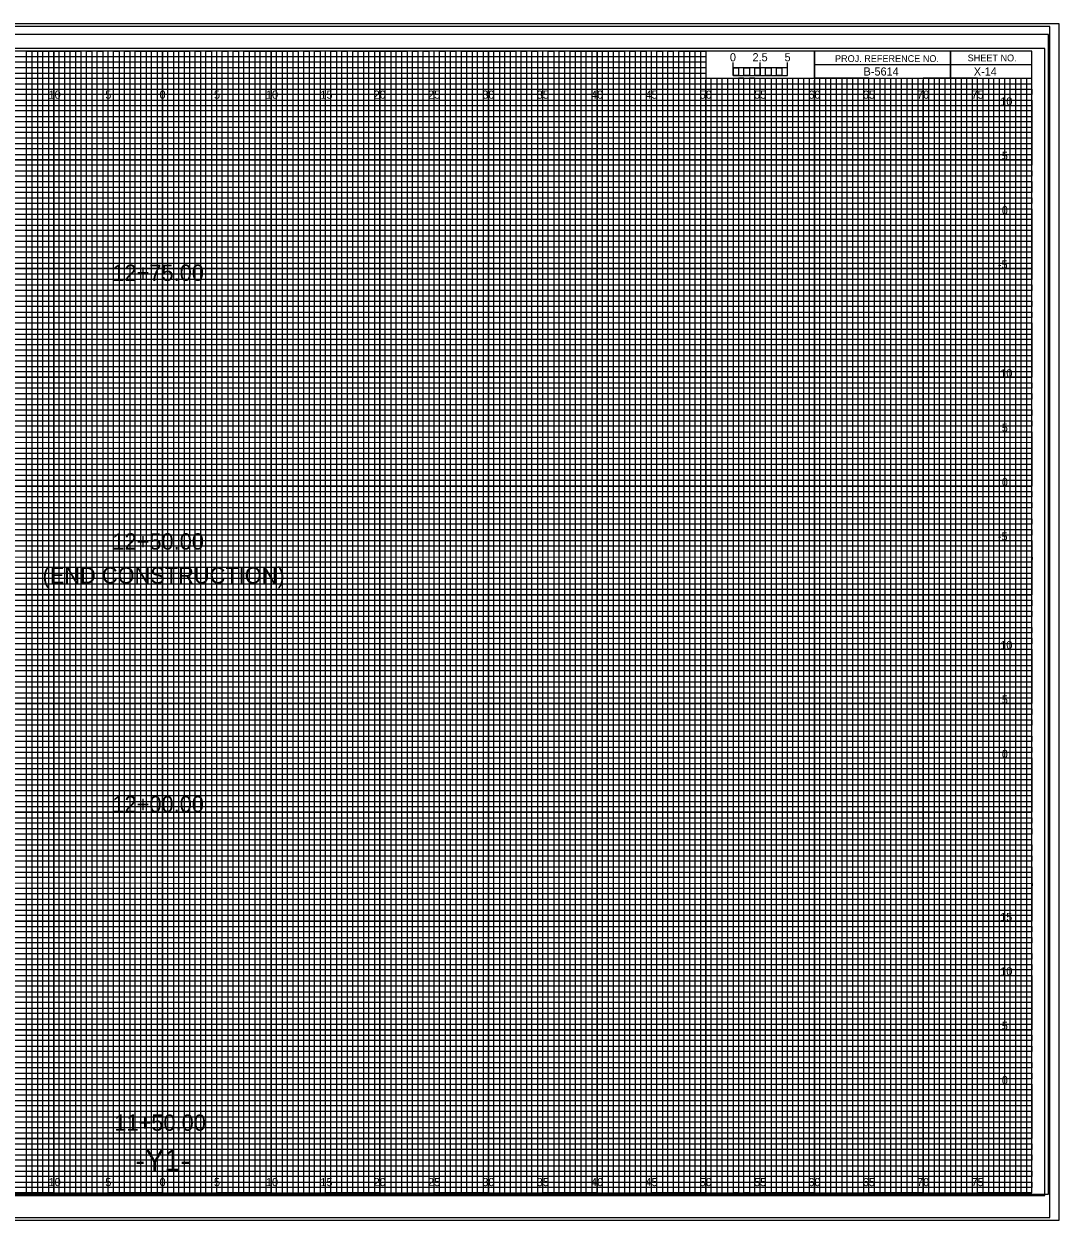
# Model space of a CAD drawing. Extents: x -8 to 162, y 108 to 218.
# Drawn here: x 67.2 to 162.5, y 107.5 to 217.5 of the extents above; entities that cross this region are included whole.
import ezdxf

# ---------------------------------------------------------------- set-up
doc = ezdxf.new("R2010")
doc.units = 0
for name, color, linetype in [('Prop XS Alignment Label', 7, 'Continuous'), ('Prop XS Bar Scale Labels', 7, 'Continuous'), ('Prop XS Elevation Labels', 7, 'Continuous'), ('Prop XS Offset Labels', 7, 'Continuous'), ('Prop XS Project Number', 7, 'Continuous'), ('Prop XS Sheet Number', 7, 'Continuous'), ('Prop XS Station Labels', 7, 'Continuous'), ('Sheet Cross Section CELL', 7, 'Continuous'), ('Sheet Cross Section Grid Major CELL', 7, 'Continuous'), ('Sheet Cross Section Grid Middle CELL', 7, 'Continuous'), ('Sheet Cross Section Grid Minor 1 CELL', 7, 'Continuous'), ('Sheet Cross Section Grid Minor 2 CELL', 7, 'Continuous'), ('Sheet Cross Section Scale CELL', 7, 'Continuous'), ('Sheet Cutting Line CELL', 7, 'Continuous'), ('Sheet DOT Grid CELL', 7, 'Continuous'), ('Sheet Plot Border Inside CELL', 7, 'Continuous'), ('Sheet Plot Border Outside CELL', 7, 'Continuous'), ('Stewart Plot Border DJ1055', 7, 'Continuous'), ('Stewart Plot Border DJ1055 Invisible', 7, 'Continuous'), ('Stewart Plot Border Xerox6279 and LJ5000', 7, 'Continuous')]:
    doc.layers.add(name, color=color, linetype=linetype)

msp = doc.modelspace()

# ---------------------------------------------------------------- linework, layer by layer
at = {"layer": 'Sheet Cross Section CELL'}
for p, q in [((152.5, 215), (152.5, 212.5)), ((152.5, 212.5), (152.5, 215)), ((160, 213.75), (140, 213.75)), ((140, 213.75), (140, 212.5)), ((140, 212.5), (160, 212.5))]:
    msp.add_line(p, q, dxfattribs=at)
for points in [[(160, 215), (0, 215), (0, 110), (160, 110)], [(140, 215), (130, 215), (130, 212.52), (140, 212.52)], [(160, 215), (140, 215), (140, 212.5), (160, 212.5)]]:
    msp.add_lwpolyline(points, close=True, dxfattribs=at)
at = {"layer": 'Sheet Cross Section Grid Major CELL'}
for p, q in [((75, 215), (70, 215)), ((70, 215), (70, 110)), ((75, 110), (75, 215)), ((85, 215), (80, 215)), ((80, 215), (80, 110)), ((85, 110), (85, 215)), ((95, 215), (90, 215)), ((90, 215), (90, 110)), ((95, 110), (95, 215)), ((105, 215), (100, 215)), ((100, 215), (100, 110)), ((105, 110), (105, 215)), ((115, 215), (110, 215)), ((110, 215), (110, 110)), ((115, 110), (115, 215)), ((125, 215), (120, 215)), ((120, 215), (120, 110)), ((125, 110), (125, 215)), ((130, 215), (130, 110)), ((135, 110), (135, 212.5)), ((145, 212.5), (140, 212.5)), ((140, 212.5), (140, 110)), ((145, 110), (145, 212.5)), ((155, 212.5), (150, 212.5)), ((150, 212.5), (150, 110)), ((155, 110), (155, 212.5)), ((70, 110), (65, 110)), ((80, 110), (75, 110)), ((90, 110), (85, 110)), ((100, 110), (95, 110)), ((110, 110), (105, 110)), ((120, 110), (115, 110)), ((130, 110), (125, 110)), ((140, 110), (135, 110)), ((150, 110), (145, 110)), ((160, 110), (155, 110)), ((160, 110), (160, 110))]:
    msp.add_line(p, q, dxfattribs=at)
for points in [[(0, 210), (160, 210), (160, 205), (0, 205)], [(0, 200), (160, 200), (160, 195), (0, 195)], [(0, 190), (160, 190), (160, 185), (0, 185)], [(0, 180), (160, 180), (160, 175), (0, 175)], [(0, 170), (160, 170), (160, 165), (0, 165)], [(0, 160), (160, 160), (160, 155), (0, 155)], [(0, 150), (160, 150), (160, 145), (0, 145)], [(0, 140), (160, 140), (160, 135), (0, 135)], [(0, 130), (160, 130), (160, 125), (0, 125)], [(0, 120), (160, 120), (160, 115), (0, 115)]]:
    msp.add_lwpolyline(points, dxfattribs=at)
at = {"layer": 'Sheet Cross Section Grid Middle CELL'}
for points in [[(62.5, 110), (67.5, 110), (67.5, 215), (72.5, 215), (72.5, 110), (77.5, 110), (77.5, 215), (82.5, 215), (82.5, 110), (87.5, 110), (87.5, 215), (92.5, 215), (92.5, 110), (97.5, 110), (97.5, 215), (102.5, 215), (102.5, 110), (107.5, 110), (107.5, 215), (112.5, 215), (112.5, 110), (117.5, 110), (117.5, 215), (122.5, 215), (122.5, 110), (127.5, 110), (127.5, 215), (129.97, 215), (130, 215), (130, 212.5), (132.5, 212.5), (132.5, 110), (137.5, 110), (137.5, 212.5), (142.5, 212.5), (142.5, 110), (147.5, 110), (147.5, 212.5), (152.5, 212.5), (152.5, 110), (157.5, 110), (157.5, 212.5)], [(0, 212.5), (137.5, 212.5)], [(0, 202.5), (160, 202.5), (160, 207.5), (0, 207.5)], [(0, 192.5), (160, 192.5), (160, 197.5), (0, 197.5)], [(0, 182.5), (160, 182.5), (160, 187.5), (0, 187.5)], [(0, 172.5), (160, 172.5), (160, 177.5), (0, 177.5)], [(0, 162.5), (160, 162.5), (160, 167.5), (0, 167.5)], [(0, 152.5), (160, 152.5), (160, 157.5), (0, 157.5)], [(0, 142.5), (160, 142.5), (160, 147.5), (0, 147.5)], [(0, 132.5), (160, 132.5), (160, 137.5), (0, 137.5)], [(0, 122.5), (160, 122.5), (160, 127.5), (0, 127.5)], [(0, 112.5), (160, 112.5), (160, 117.5), (0, 117.5)]]:
    msp.add_lwpolyline(points, dxfattribs=at)
at = {"layer": 'Sheet Cross Section Grid Minor 1 CELL'}
for p, q in [((0, 214.5), (130, 214.5)), ((130, 213.99), (0, 213.99)), ((0, 213.5), (130, 213.5)), ((130, 214.5), (130, 213.99)), ((130, 213.5), (130, 212.94)), ((130, 212.94), (0, 212.94)), ((0, 212), (160, 212))]:
    msp.add_line(p, q, dxfattribs=at)
for points in [[(0, 211.5), (135, 211.5), (160, 211.5), (160, 211), (0, 211)], [(0, 210.5), (160, 210.5), (160, 209.5), (0, 209.5)], [(0, 209), (160, 209), (160, 208.5), (0, 208.49)], [(0, 208), (160, 208), (160, 207), (0, 207)], [(0, 206.5), (160, 206.5), (160, 206), (0, 206)], [(0, 205.5), (160, 205.5), (160, 204.5), (0, 204.5)], [(0, 204), (160, 204), (160, 203.5), (0, 203.5)], [(0, 203), (160, 203), (160, 202), (0, 202)], [(0, 201.5), (160, 201.5), (160, 201), (0, 201)], [(0, 200.5), (160, 200.5), (160, 199.5), (0, 199.5)], [(0, 199), (160, 199), (160, 198.5), (0, 198.5)], [(0, 198), (160, 198), (160, 196.97), (160, 196.5), (160, 196), (0, 196)], [(0, 197), (160, 197), (160, 196.5), (0, 196.5)], [(0, 195.5), (160, 195.5), (160, 194.5), (0, 194.52)], [(0, 194.52), (160, 194.5), (160, 194), (0, 194)], [(0, 193.5), (160, 193.5), (160, 193), (0, 193)], [(0, 192), (160, 192), (160, 191.5), (0, 191.5)], [(0, 191), (160, 191), (160, 190.5), (0, 190.5)], [(-0.04, 189.44), (160, 189.44), (160, 188.94), (-0.04, 188.94)], [(0, 188.5), (160, 188.5), (160, 188), (0, 188)], [(0, 187), (160, 187), (160, 186.5), (0, 186.5)], [(0, 186), (160, 186), (160, 185.5), (0, 185.5)], [(0, 184.5), (160, 184.5), (160, 184), (0, 184)], [(0, 183.5), (160, 183.5), (160, 183), (0, 183)], [(0, 182), (160, 182), (160, 181.5), (0, 181.5)], [(0, 181), (160, 181), (160, 180.5), (0, 180.5)], [(0, 179.5), (160, 179.5), (160, 178.99), (0, 179)], [(0, 178.5), (160, 178.5), (160, 178), (0, 178)], [(0, 177), (160, 177), (160, 176.5), (0, 176.5)], [(0, 176), (160, 176), (160, 175.5), (0, 175.5)], [(0, 174.5), (160, 174.5), (160, 174), (0, 174)], [(0, 173.5), (160, 173.5), (160, 173), (0, 173)], [(0, 172), (160, 172), (160, 171.5), (0, 171.5)], [(0, 171), (160, 171), (160, 170.5), (0, 170.5)], [(0, 169.5), (160, 169.5), (160, 169), (0, 169)], [(0, 168.5), (160.03, 168.46), (160, 168), (0, 168)], [(0, 167), (160, 167), (160, 166.5), (0, 166.5)], [(0, 166), (160, 166), (160, 165.5), (0, 165.5)], [(0, 164.5), (160, 164.5), (160, 164), (0, 164)], [(0, 163.5), (160, 163.5), (160, 163), (0, 163)], [(0, 162), (160, 162), (160, 161.5), (0, 161.5)], [(0, 161), (160, 161), (160, 160.5), (0, 160.5)], [(0, 159.5), (160, 159.5), (160, 159), (0, 159)], [(0, 158.5), (160, 158.5), (160, 158), (0, 158)], [(0, 157), (160, 157), (160, 156.5), (0, 156.5)], [(0, 156), (160, 156), (160, 155.5), (0, 155.5)], [(0, 154.5), (160, 154.5), (160, 154), (0, 154)], [(0, 153.5), (160, 153.5), (160, 153), (0, 153)], [(0, 152), (160, 152), (160, 151.5), (0, 151.5)], [(0, 151), (160, 151), (160, 150.5), (0, 150.5)], [(0, 149.5), (160, 149.5), (160, 148.99), (0, 149)], [(0, 148.5), (160, 148.5), (160, 148), (0, 148)], [(0, 147), (160, 147), (160, 146.5), (0, 146.5)], [(0, 146), (160, 146), (160, 145.5), (0, 145.5)], [(0, 144.5), (160, 144.5), (160, 144), (0, 144)], [(0, 143.5), (160, 143.5), (160, 143), (0, 143)], [(0, 142), (160, 142), (160, 141.5), (0, 141.5)], [(0, 141), (160, 141), (160, 140.5), (0, 140.5)], [(0, 139.5), (160, 139.5), (160, 139), (0, 139)], [(0, 138.5), (160.03, 138.46), (160, 138), (0, 138)], [(0, 137), (160, 137), (160, 136.5), (0, 136.5)], [(0, 136), (160, 136), (160, 135.5), (0, 135.5)], [(0, 134.5), (160, 134.5), (160, 134), (0, 134)], [(0, 133.5), (160, 133.5), (160, 133), (0, 133)], [(0, 132), (160, 132), (160, 131.5), (0, 131.5)], [(0, 131), (160, 131), (160, 130.5), (0, 130.5)], [(0, 129.5), (160, 129.5), (160, 129), (0, 129)], [(0, 128.5), (160, 128.5), (160, 128), (0, 128)], [(0, 127), (160, 127), (160, 126.5), (0, 126.5)], [(0, 126), (160, 126), (160, 125.5), (0, 125.5)], [(0, 124.5), (160, 124.5), (160, 124), (0, 124)], [(0, 123.5), (160, 123.5), (160, 123), (0, 123)], [(0, 122), (160, 122), (160, 121.5), (0, 121.5)], [(0, 121), (160, 121), (160, 120.5), (0, 120.5)], [(0, 119.5), (160, 119.5), (160, 119), (0, 119)], [(0, 118.5), (160, 118.5), (160, 118), (0, 118)], [(0, 117), (160, 117), (160, 116.5), (0, 116.5)], [(0, 116), (160, 116), (160, 115.5), (0, 115.5)], [(0, 114.5), (160, 114.5), (160, 114), (0, 114)], [(0, 113.5), (160, 113.5), (160, 113), (0, 113)], [(0, 112), (160, 112), (160, 111.5), (0, 111.5)], [(0, 111), (160, 111), (160, 110.5), (0, 110.5)]]:
    msp.add_lwpolyline(points, dxfattribs=at)
at = {"layer": 'Sheet Cross Section Grid Minor 2 CELL'}
for p, q in [((133.5, 212.5), (133, 212.5)), ((133, 212.5), (133, 110)), ((133.5, 110), (133.5, 212.5)), ((134.5, 212.5), (134, 212.5)), ((134, 212.5), (134, 110)), ((134.5, 110), (134.5, 212.5)), ((133, 110), (132.5, 110)), ((134, 110), (133.5, 110))]:
    msp.add_line(p, q, dxfattribs=at)
for points in [[(67.5, 110), (68, 110), (68, 215), (68.5, 215), (68.5, 110)], [(68.5, 110), (69, 110), (69, 215), (69.5, 215), (69.5, 110)], [(70, 110), (70.5, 110), (70.5, 215), (71, 215), (71, 110)], [(71, 110), (71.5, 110), (71.5, 215), (72, 215), (72, 110)], [(72.5, 110), (73, 110), (73, 215), (73.5, 215), (73.5, 110)], [(73.5, 110), (74, 110), (74, 215), (74.5, 215), (74.5, 110)], [(75, 110), (75.5, 110), (75.5, 215), (76, 215), (76, 110)], [(76, 110), (76.5, 110), (76.5, 215), (77, 215), (77, 110)], [(77.5, 110), (78, 110), (78, 215), (78.5, 215), (78.5, 110)], [(78.5, 110), (79, 110), (79, 215), (79.5, 215), (79.5, 110)], [(80, 110), (80.5, 110), (80.5, 215), (81, 215), (81, 110)], [(81, 110), (81.5, 110), (81.5, 215), (82, 215), (82, 110)], [(82.5, 110), (83, 110), (83, 215), (83.5, 215), (83.5, 110)], [(83.5, 110), (84, 110), (84, 215), (84.5, 215), (84.5, 110)], [(85, 110), (85.5, 110), (85.5, 215), (86, 215), (86, 110)], [(86, 110), (86.5, 110), (86.5, 215), (87, 215), (87, 110)], [(87.5, 110), (88, 110), (88, 215), (88.5, 215), (88.5, 110)], [(88.5, 110), (89, 110), (89, 215), (89.5, 215), (89.5, 110)], [(90, 110), (90.5, 110), (90.5, 215), (91, 215), (91, 110)], [(91, 110), (91.5, 110), (91.5, 215), (92, 215), (92, 110)], [(92.5, 110), (93, 110), (93, 215), (93.5, 215), (93.5, 110)], [(93.5, 110), (94, 110), (94, 215), (94.5, 215), (94.5, 110)], [(95, 110), (95.5, 110), (95.5, 215), (96, 215), (96, 110)], [(96, 110), (96.5, 110), (96.5, 215), (97, 215), (97, 110)], [(97.5, 110), (98, 110), (98, 215), (98.5, 215), (98.5, 110)], [(98.5, 110), (99, 110), (99, 215), (99.5, 215), (99.5, 110)], [(100, 110), (100.5, 110), (100.5, 215), (101, 215), (101, 110)], [(101, 110), (101.5, 110), (101.5, 215), (102, 215), (102, 110)], [(102.5, 110), (103, 110), (103, 215), (103.5, 215), (103.5, 110)], [(103.5, 110), (104, 110), (104, 215), (104.5, 215), (104.5, 110)], [(105, 110), (105.5, 110), (105.5, 215), (106, 215), (106, 110)], [(106, 110), (106.5, 110), (106.5, 215), (107, 215), (107, 110)], [(107.5, 110), (108, 110), (108, 215), (108.5, 215), (108.5, 110)], [(108.5, 110), (109, 110), (109, 215), (109.5, 215), (109.5, 110)], [(110, 110), (110.5, 110), (110.5, 215), (111, 215), (111, 110)], [(111, 110), (111.5, 110), (111.5, 215), (112, 215), (112, 110)], [(112.5, 110), (113, 110), (113, 215), (113.5, 215), (113.5, 110)], [(113.5, 110), (114, 110), (114, 215), (114.5, 215), (114.5, 110)], [(115, 110), (115.5, 110), (115.5, 215), (116, 215), (116, 110)], [(116, 110), (116.5, 110), (116.5, 215), (117, 215), (117, 110)], [(117.5, 110), (118, 110), (118, 215), (118.5, 215), (118.5, 110)], [(118.5, 110), (119, 110), (119, 215), (119.5, 215), (119.5, 110)], [(120, 110), (120.5, 110), (120.5, 215), (121, 215), (121, 110)], [(121, 110), (121.5, 110), (121.5, 215), (122, 215), (122, 110)], [(122.5, 110), (123, 110), (123, 215), (123.5, 215), (123.5, 110)], [(123.5, 110), (124, 110), (124, 215), (124.5, 215), (124.5, 110)], [(125, 110), (125.5, 110), (125.5, 215), (126, 215), (126, 110)], [(126, 110), (126.5, 110), (126.5, 215), (127, 215), (127, 110)], [(127.5, 110), (128, 110), (128, 215), (128.5, 215), (128.5, 110)], [(128.5, 110), (129, 110), (129, 215), (129.5, 215), (129.5, 110)], [(130, 110), (130.5, 110), (130.5, 212.5), (131.01, 212.5), (131.01, 110)], [(131, 110), (131.5, 110), (131.5, 212.5), (132, 212.5), (132, 110)], [(135, 110), (135.49, 110), (135.49, 212.5), (136, 212.5), (136, 110)], [(136, 110), (136.5, 110), (136.5, 212.5), (137.03, 212.5), (137.03, 110)], [(137.5, 110), (138, 110), (138, 212.5), (138.5, 212.5), (138.5, 110)], [(138.5, 110), (139, 110), (139, 212.5), (139.5, 212.5), (139.5, 110)], [(140, 110), (140.5, 110), (140.5, 212.5), (141, 212.5), (141, 110)], [(141, 110), (141.5, 110), (141.5, 212.5), (142, 212.5), (142, 110)], [(142.5, 110), (143, 110), (143, 212.5), (143.5, 212.5), (143.5, 110)], [(143.5, 110), (144, 110), (144, 212.5), (144.5, 212.5), (144.5, 110)], [(145, 110), (145.5, 110), (145.5, 212.5), (146, 212.5), (146, 110)], [(146, 110), (146.5, 110), (146.5, 212.5), (147, 212.5), (147, 110)], [(147.5, 110), (148, 110), (148, 212.5), (148.5, 212.5), (148.5, 110)], [(148.5, 110), (149, 110), (149, 212.5), (149.5, 212.5), (149.5, 110)], [(150, 110), (150.5, 110), (150.5, 212.5), (151, 212.5), (151, 110)], [(151, 110), (151.5, 110), (151.5, 212.5), (152, 212.5), (152, 110)], [(152.5, 110), (153, 110), (153, 212.5), (153.5, 212.5), (153.5, 110)], [(153.5, 110), (154, 110), (154, 212.5), (154.5, 212.5), (154.5, 110)], [(155, 110), (155.5, 110), (155.5, 212.5), (156, 212.5), (156, 110)], [(156, 110), (156.5, 110), (156.5, 212.5), (157, 212.5), (157, 110)], [(157.5, 110), (158, 110), (158, 212.5), (158.5, 212.5), (158.5, 110)], [(158.5, 110), (159, 110), (159, 212.5), (159.5, 212.5), (159.5, 110)]]:
    msp.add_lwpolyline(points, dxfattribs=at)
at = {"layer": 'Sheet Cross Section Scale CELL'}
for p, q in [((132.5, 212.75), (132.5, 213.95)), ((132.5, 213.45), (132.5, 213.95)), ((135, 212.75), (135, 213.95)), ((137.5, 212.75), (137.5, 213.95)), ((137.5, 213.45), (137.5, 213.95))]:
    msp.add_line(p, q, dxfattribs=at)
for points in [[(137.5, 213.45), (132.5, 213.45), (132.5, 212.75), (137.5, 212.75)], [(132.5, 213.45), (133, 213.45), (133, 212.75), (132.5, 212.75)], [(133.5, 213.45), (134, 213.45), (134, 212.75), (133.5, 212.75)], [(134.5, 213.45), (135, 213.45), (135, 212.75), (134.5, 212.75)], [(135.5, 213.45), (136, 213.45), (136, 212.75), (135.5, 212.75)], [(136.5, 213.45), (137, 213.45), (137, 212.75), (136.5, 212.75)]]:
    msp.add_lwpolyline(points, close=True, dxfattribs=at)
at = {"layer": 'Sheet Cutting Line CELL'}
for p, q in [((161.65, 217.25), (-6.7, 217.25)), ((-6.7, 107.75), (161.65, 107.75))]:
    msp.add_line(p, q, dxfattribs=at)
at = {"layer": 'Sheet DOT Grid CELL'}
for p, q in [((70, 110), (70, 215)), ((75, 110), (75, 215)), ((80, 110), (80, 215)), ((85, 110), (85, 215)), ((90, 110), (90, 215)), ((95, 110), (95, 215)), ((100, 110), (100, 215)), ((105, 110), (105, 215)), ((110, 110), (110, 215)), ((115, 110), (115, 215)), ((120, 110), (120, 215)), ((125, 110), (125, 215)), ((130, 110), (130, 212.34)), ((135, 110), (135, 212.34)), ((140, 110), (140, 212.34)), ((145, 110), (145, 212.34)), ((150, 110), (150, 212.34)), ((155, 110), (155, 212.34)), ((0, 210), (160, 210)), ((0, 205), (160, 205)), ((0, 200), (160, 200)), ((0, 195), (160, 195)), ((0, 190), (160, 190)), ((0, 185), (160, 185)), ((0, 180), (160, 180)), ((0, 175), (160, 175)), ((0, 170), (160, 170)), ((0, 165), (160, 165)), ((0, 160), (160, 160)), ((0, 155), (160, 155)), ((0, 150), (160, 150)), ((0, 145), (160, 145)), ((0, 140), (160, 140)), ((0, 135), (160, 135)), ((0, 130), (160, 130)), ((0, 125), (160, 125)), ((0, 120), (160, 120)), ((0, 115), (160, 115))]:
    msp.add_line(p, q, dxfattribs=at)
at = {"layer": 'Sheet Plot Border Inside CELL'}
msp.add_lwpolyline([(-5.4, 109.75), (161.2, 109.75), (161.2, 215.25), (-5.4, 215.25)], close=True, dxfattribs=at)
at = {"layer": 'Sheet Plot Border Outside CELL'}
msp.add_lwpolyline([(-6.7, 107.75), (161.65, 107.75), (161.65, 217.25), (-6.7, 217.25)], close=True, dxfattribs=at)
at = {"layer": 'Stewart Plot Border DJ1055'}
msp.add_lwpolyline([(161.52, 216.53), (-6.52, 216.53), (-6.52, 109.87), (161.52, 109.87)], close=True, dxfattribs=at)
at = {"layer": 'Stewart Plot Border DJ1055 Invisible'}
msp.add_lwpolyline([(161.52, 216.53), (-6.52, 216.53), (-6.52, 109.87), (161.52, 109.87)], close=True, dxfattribs=at)
at = {"layer": 'Stewart Plot Border Xerox6279 and LJ5000'}
msp.add_lwpolyline([(-7.5, 107.5), (162.5, 107.5), (162.5, 217.5), (-7.5, 217.5)], close=True, dxfattribs=at)

# ---------------------------------------------------------------- texts
at = {"layer": 'Prop XS Alignment Label'}
msp.add_text('-Y1-', height=2, dxfattribs=at).set_placement((77.5, 112))
at = {"layer": 'Prop XS Bar Scale Labels'}
for s, p in [('2.5', (134.29, 214.06)), ('5', (137.24, 214.06))]:
    msp.add_text(s, height=0.75, dxfattribs=at).set_placement(p)
at = {"layer": 'Prop XS Elevation Labels'}
for s, p in [('10', (157.09, 210)), ('5', (157.23, 205)), ('0', (157.23, 200)), ('-5', (156.87, 195)), ('10', (157.09, 185)), ('5', (157.23, 180)), ('0', (157.23, 175)), ('-5', (156.87, 170)), ('10', (157.09, 160)), ('5', (157.23, 155)), ('0', (157.23, 150)), ('15', (157.08, 135)), ('10', (157.09, 130)), ('5', (157.23, 125)), ('0', (157.23, 120))]:
    msp.add_text(s, height=0.75, dxfattribs=at).set_placement(p)
at = {"layer": 'Prop XS Offset Labels'}
for s, p in [('10', (69.52, 210.62)), ('5', (74.74, 210.62)), ('0', (79.73, 210.62)), ('0', (79.73, 210.62)), ('5', (84.74, 210.62)), ('10', (89.52, 210.62)), ('15', (94.53, 210.62)), ('20', (99.43, 210.62)), ('25', (104.44, 210.62)), ('30', (109.43, 210.62)), ('35', (114.44, 210.62)), ('40', (119.43, 210.62)), ('45', (124.44, 210.62)), ('50', (129.43, 210.62)), ('55', (134.44, 210.62)), ('60', (139.43, 210.62)), ('65', (144.44, 210.62)), ('70', (149.43, 210.62)), ('75', (154.44, 210.62)), ('10', (69.52, 110.62)), ('5', (74.74, 110.62)), ('0', (79.73, 110.62)), ('0', (79.73, 110.62)), ('5', (84.74, 110.62)), ('10', (89.52, 110.62)), ('15', (94.53, 110.62)), ('20', (99.43, 110.62)), ('25', (104.44, 110.62)), ('30', (109.43, 110.62)), ('35', (114.44, 110.62)), ('40', (119.43, 110.62)), ('45', (124.44, 110.62)), ('50', (129.43, 110.62)), ('55', (134.44, 110.62)), ('60', (139.43, 110.62)), ('65', (144.44, 110.62)), ('70', (149.43, 110.62)), ('75', (154.44, 110.62))]:
    msp.add_text(s, height=0.75, dxfattribs=at).set_placement(p)
at = {"layer": 'Prop XS Project Number'}
msp.add_text('B-5614', height=0.75, dxfattribs=at).set_placement((144.51, 212.75))
at = {"layer": 'Prop XS Sheet Number'}
msp.add_text('X-14', height=0.75, dxfattribs=at).set_placement((154.65, 212.75))
at = {"layer": 'Prop XS Station Labels'}
for s, p in [('12+75.00', (75.39, 193.87)), ('12+50.00', (75.39, 169.16)), ('(END CONSTRUCTION)', (68.96, 166.04)), ('12+00.00', (75.39, 145)), ('11+50.00', (75.57, 115.71))]:
    msp.add_text(s, height=1.5, dxfattribs=at).set_placement(p)
at = {"layer": 'Sheet Cross Section CELL'}
for s, p in [('PROJ. REFERENCE NO.', (141.88, 214)), ('SHEET NO.', (154.09, 214.06))]:
    msp.add_text(s, height=0.625, dxfattribs=at).set_placement(p)
at = {"layer": 'Sheet Cross Section Scale CELL'}
msp.add_text('0', height=0.75, dxfattribs=at).set_placement((132.21, 214.06))

doc.saveas('drawing.dxf')
